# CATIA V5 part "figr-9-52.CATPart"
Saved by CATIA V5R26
Part number: Part1
Bounding box of the stored display mesh (mm): x -121 to 121, y -90 to 90, z -40 to 40
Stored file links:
  D:\_Deepak\CATIA\CATIA V5-6R2016_Deepak\Resources\Part files\Partfiles\c09_catia_v5_6r2016_prt\figr-9-52.CATPart
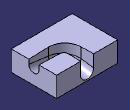
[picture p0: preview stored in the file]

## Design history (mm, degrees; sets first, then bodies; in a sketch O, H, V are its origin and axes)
Body1 (main body)
  Sketch1 on yz-plane, origin (0, 0, 0), H (0, 1, 0), V (0, 0, 1)
    line L1 (-90, 40) -> (90, 40)
    line L2 (90, 40) -> (90, -40)
    line L3 (90, -40) -> (-90, -40)
    line L4 (-90, -40) -> (-90, 40)
    axis line L5 (90, -40) -> (-90, 40)
    horizontal: L1 H, L3 H
    vertical: L2 V, L4 V
    midpoint: O L5
  Pad1: profile Sketch1, direction (1, 0, 0), length 121, mirrored extent
  Loft1: solid, Sections (Sketch4; Sketch3), Spine Sketch2, SectionCouplingPoints ({coupling CouplingPoints (vertex [element of Sketch4 | element of Sketch4]; vertex [element of Sketch3 | element of Sketch3])}; {coupling CouplingPoints (vertex [element of Sketch4 | element of Sketch4]; vertex [element of Sketch3 | element of Sketch3])}; {coupling CouplingPoints (vertex [element of Sketch4 | element of Sketch4]; vertex [element of Sketch3 | element of Sketch3])})
  Sketch2 on face of Pad1, origin (0, 0, 40), H (1, 0, 0), V (0, 1, 0)
    point P1 (121, 0)
    line L1 (121, 0) -> (40.984, 0)
    arc A1 centre (40.984, 40.984) radius 40.984 from (40.984, 0) to (0, 40.984) cw
    line L2 (0, 40.984) -> (0, 90)
    point P5 (0, 90)
    reference projected line E1 (121, 20) -> (121, -20) from edge of Sketch4
    reference projected line E2 (-25.9516, 90) -> (25.9516, 90) from edge of Sketch3
    coincidence: P1 H, P1 E1, P5 E2
    horizontal: L1 H
    tangency: A1 L1, L2 A1
    vertical: L2 V
  Sketch3 on face of Pad1, origin (0, 90, 0), H (-1, 0, 0), V (0, 0, 1)
    line L1 (-25.9516, 40) -> (-25.9516, -8.0968)
    arc A1 centre (0, -8.0968) radius 25.9516 from (-25.9516, -8.0968) to (25.9516, -8.0968) ccw
    point P3 (0, -8.0968)
    line L2 (25.9516, -8.0968) -> (25.9516, 40)
    line L3 (25.9516, 40) -> (-25.9516, 40)
    reference projected line E1 (121, 40) -> (-121, 40) from edge [face of Pad1 | face of Pad1]
    vertical: L1 V, L2 V
    tangency: A1 L1, L2 A1
    horizontal: L3 H
    coincidence: P3 V, L3 E1
  Sketch4 on face of Pad1, origin (121, 0, 0), H (0, 1, 0), V (0, 0, 1)
    line L1 (-20, 40) -> (-20, 21.9917)
    arc A1 centre (0, 21.9917) radius 20 from (-20, 21.9917) to (20, 21.9917) ccw
    point P3 (0, 21.9917)
    line L2 (20, 21.9917) -> (20, 40)
    line L3 (20, 40) -> (-20, 40)
    reference projected line E1 (90, 40) -> (-90, 40) from edge [face of Pad1 | face of Pad1]
    vertical: L1 V, L2 V
    tangency: A1 L1, L2 A1
    horizontal: L3 H
    coincidence: P3 V, L3 E1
